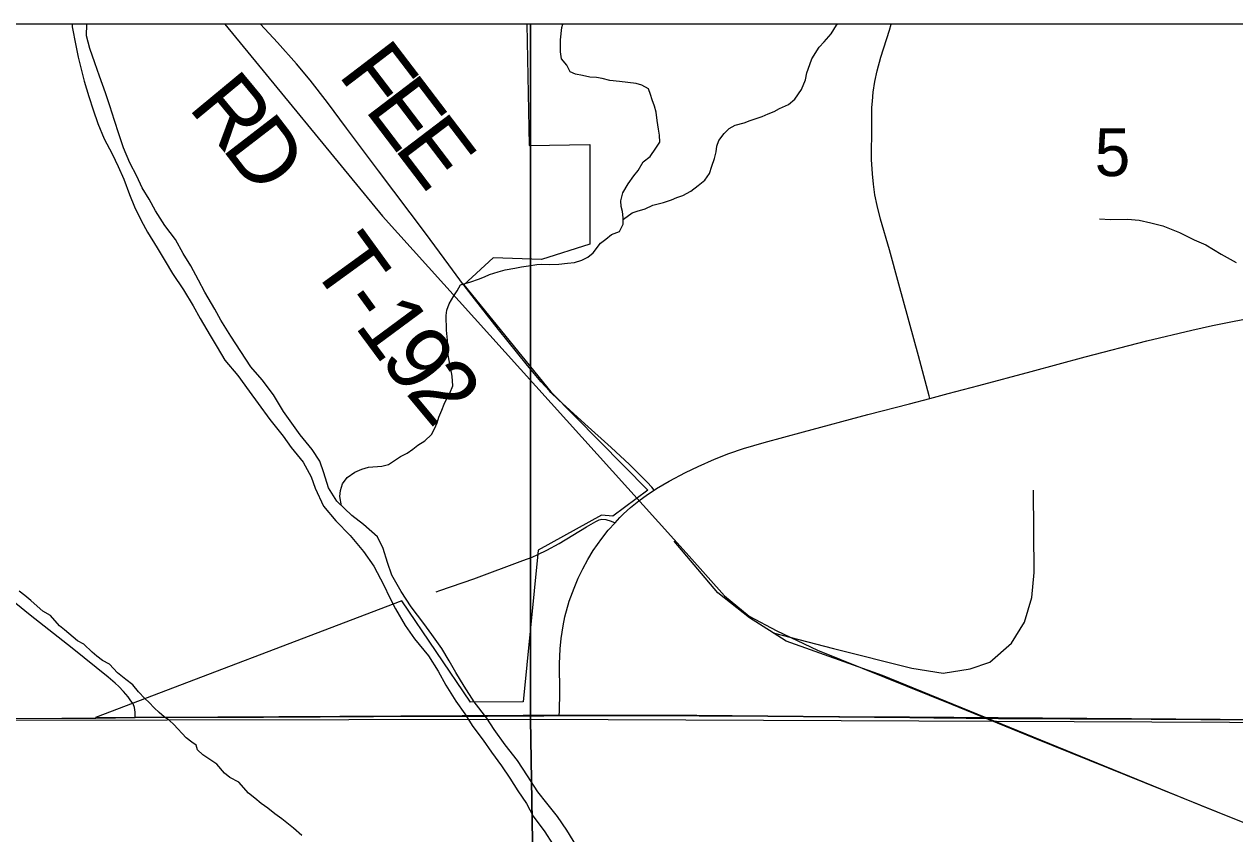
# Model space of a CAD drawing. Extents: x 0 to 34, y 0 to 22.
# Drawn here: x 6.446 to 7.505, y 20.191 to 20.9 of the extents above; entities that cross this region are included whole.
import ezdxf

# ---------------------------------------------------------------- set-up
doc = ezdxf.new("R2010")
doc.units = 0
for name, color, linetype in [('GM_X_City_Street', 7, 'Continuous'), ('GM_X_County_Road', 7, 'Continuous'), ('GM_X_Major_River', 7, 'Continuous'), ('GM_X_Minor_River', 7, 'Continuous'), ('GM_X_Rail_Line', 7, 'Continuous'), ('GM_X_Section', 7, 'Continuous'), ('GM_X_Section_Text', 7, 'Continuous'), ('GM_X_State_Route', 7, 'Continuous'), ('GM_X_Township_Road', 7, 'Continuous'), ('GM_X_Township_Road_Text', 7, 'Continuous'), ('GM_X_Unincorporated', 7, 'Continuous')]:
    doc.layers.add(name, color=color, linetype=linetype)

msp = doc.modelspace()

# ---------------------------------------------------------------- linework, layer by layer
at = {"layer": 'GM_X_City_Street'}
for points in [[(7.2385, 20.5724), (7.2379, 20.5746), (7.2285, 20.6096), (7.2112, 20.6725), (7.203, 20.7024), (7.1953, 20.7293), (7.1923, 20.7414), (7.1904, 20.7505), (7.189, 20.7598), (7.1881, 20.7691), (7.1875, 20.7816), (7.1876, 20.8112), (7.1878, 20.8269), (7.1881, 20.8325), (7.1888, 20.8406), (7.1902, 20.8499), (7.1922, 20.859), (7.1956, 20.871), (7.2031, 20.8947), (7.2045, 20.9)], [(6.8955, 20.4359), (6.9031, 20.4395), (6.9141, 20.4454), (6.938, 20.4599), (6.9461, 20.4645), (6.9491, 20.466), (6.9513, 20.4666), (6.955, 20.4663), (6.9595, 20.4648), (6.9629, 20.4636)]]:
    msp.add_lwpolyline(points, dxfattribs=at)
at = {"layer": 'GM_X_County_Road'}
for points in [[(6.382, 20.2915), (6.3969, 20.2916), (6.4231, 20.2921), (6.4788, 20.2924), (6.5063, 20.2926)], [(6.5063, 20.2926), (6.5086, 20.2926), (6.5431, 20.293)], [(6.5431, 20.293), (6.6552, 20.2934), (6.705, 20.2938), (6.7982, 20.2942), (6.8262, 20.2942)], [(6.8262, 20.2942), (6.8512, 20.2942), (6.8773, 20.2944), (6.8828, 20.2944), (6.8848, 20.2945)], [(6.8848, 20.2945), (6.9006, 20.2946), (6.9141, 20.2947)], [(6.9141, 20.2947), (7.0344, 20.2947), (7.2208, 20.293), (7.242, 20.2928)], [(7.242, 20.2928), (7.2985, 20.2922), (7.3611, 20.292)], [(7.3611, 20.292), (7.373, 20.292), (7.432, 20.2916), (7.519, 20.291), (7.5594, 20.2907), (7.5702, 20.2906)]]:
    msp.add_lwpolyline(points, dxfattribs=at)
at = {"layer": 'GM_X_Major_River'}
for points in [[(6.4877, 20.9), (6.4879, 20.8977), (6.491, 20.8814), (6.493, 20.8712), (6.4984, 20.85), (6.5023, 20.8367), (6.5062, 20.825), (6.5104, 20.8129), (6.5158, 20.7997), (6.5227, 20.7864), (6.5281, 20.7755), (6.5331, 20.7642), (6.5381, 20.7509), (6.5424, 20.74), (6.5481, 20.7282), (6.5539, 20.718), (6.5623, 20.7041), (6.5692, 20.6924), (6.5757, 20.6818), (6.5853, 20.6675), (6.5937, 20.6535), (6.5998, 20.6422), (6.6087, 20.6274), (6.6148, 20.6172), (6.6213, 20.6059), (6.6328, 20.5924), (6.6427, 20.5788), (6.6507, 20.5678), (6.6607, 20.5539), (6.6725, 20.5392), (6.6794, 20.5294), (6.6901, 20.5166), (6.697, 20.5037), (6.7005, 20.4939), (6.7078, 20.478), (6.7185, 20.4652), (6.7311, 20.4524), (6.7429, 20.4385), (6.7517, 20.4256), (6.7605, 20.409), (6.7655, 20.3984), (6.7709, 20.3882), (6.7793, 20.3735), (6.7874, 20.3618), (6.7996, 20.3471), (6.808, 20.3335), (6.8149, 20.3214), (6.8237, 20.3075), (6.8314, 20.2962), (6.8386, 20.2852), (6.8474, 20.2731), (6.8547, 20.2626), (6.8635, 20.2509), (6.8708, 20.2399), (6.878, 20.229), (6.8853, 20.2177), (6.8914, 20.2067), (6.9014, 20.1931), (6.9083, 20.1826)], [(6.5609, 20.7367), (6.5552, 20.7469), (6.5491, 20.7567), (6.5445, 20.7669), (6.5383, 20.7786), (6.5329, 20.7918), (6.5287, 20.8039), (6.5248, 20.8157), (6.5209, 20.8285), (6.5171, 20.8399), (6.5117, 20.8546), (6.5078, 20.866), (6.5032, 20.8788), (6.5004, 20.8898), (6.5007, 20.9)], [(6.9295, 20.1801), (6.9207, 20.1944), (6.9127, 20.2065), (6.9031, 20.2182), (6.8955, 20.228), (6.8863, 20.242), (6.8775, 20.2555), (6.8668, 20.2691), (6.8572, 20.2827), (6.8507, 20.2925), (6.8396, 20.3068), (6.8308, 20.3204), (6.8235, 20.3325), (6.8178, 20.3427), (6.8113, 20.3536), (6.8025, 20.3657), (6.7956, 20.3755), (6.7845, 20.3899), (6.7757, 20.4034), (6.7677, 20.4178), (6.7638, 20.4288), (6.7599, 20.4409), (6.7549, 20.4511), (6.7427, 20.462), (6.7325, 20.4699), (6.7195, 20.4823), (6.7122, 20.494), (6.708, 20.5072), (6.7045, 20.5174), (6.698, 20.5276), (6.6873, 20.5404), (6.6727, 20.5608), (6.6639, 20.5755), (6.654, 20.5887), (6.6441, 20.6), (6.6353, 20.6136), (6.6268, 20.6268), (6.618, 20.6408), (6.6127, 20.6506), (6.6039, 20.6653), (6.5985, 20.6759), (6.5916, 20.6884), (6.5851, 20.6993), (6.5782, 20.7114), (6.569, 20.7238), (6.5609, 20.7367)]]:
    msp.add_lwpolyline(points, dxfattribs=at)
at = {"layer": 'GM_X_Minor_River'}
for points in [[(6.7234, 20.4785), (6.7221, 20.4865), (6.7228, 20.4918), (6.7243, 20.4975), (6.7284, 20.5033), (6.7352, 20.5079), (6.7412, 20.5106), (6.7473, 20.5122), (6.7587, 20.5132), (6.7647, 20.5144), (6.7753, 20.5214), (6.781, 20.5245), (6.7859, 20.528), (6.7904, 20.5314), (6.7964, 20.5353), (6.8024, 20.5407), (6.805, 20.5457), (6.8072, 20.551), (6.8087, 20.556), (6.8113, 20.5621), (6.8135, 20.5674), (6.8157, 20.5724), (6.8183, 20.577), (6.8209, 20.5835), (6.8204, 20.5918), (6.8192, 20.5983), (6.8179, 20.6055), (6.8167, 20.6119), (6.8163, 20.618), (6.8162, 20.6233), (6.8153, 20.632), (6.8151, 20.645), (6.8158, 20.6495), (6.8177, 20.6552), (6.8218, 20.6621), (6.8248, 20.6667), (6.8277, 20.6717), (6.8368, 20.6745), (6.8433, 20.6769), (6.8486, 20.6788), (6.8531, 20.6808), (6.8607, 20.6832), (6.8667, 20.6848), (6.8751, 20.6864), (6.8812, 20.6876), (6.8872, 20.6885), (6.8944, 20.6897), (6.899, 20.6898), (6.9058, 20.6895), (6.9138, 20.69), (6.9214, 20.6908), (6.9275, 20.6913), (6.9339, 20.6933), (6.9392, 20.696), (6.9437, 20.6998), (6.9501, 20.7083), (6.955, 20.7118), (6.9599, 20.716), (6.9667, 20.7184), (6.97, 20.7249), (6.97, 20.7306), (6.9695, 20.7359), (6.9683, 20.7404), (6.9679, 20.7454), (6.9697, 20.7522), (6.9745, 20.7603), (6.9794, 20.7672), (6.9831, 20.7718), (6.9876, 20.7794), (6.9936, 20.7841), (6.9985, 20.7914), (7.0022, 20.7967), (7.0017, 20.8028), (7.0009, 20.8081), (6.9997, 20.8157), (6.9988, 20.8229), (6.9976, 20.8282), (6.9953, 20.8339), (6.9941, 20.8384), (6.9921, 20.8433), (6.9863, 20.8467), (6.9814, 20.8481), (6.9741, 20.8488), (6.9669, 20.8498), (6.9585, 20.8508), (6.9517, 20.8523), (6.9467, 20.8533), (6.941, 20.8536), (6.9345, 20.8551), (6.9284, 20.8561), (6.9238, 20.8584), (6.9207, 20.864), (6.9161, 20.8696), (6.9152, 20.8757), (6.9151, 20.8863), (6.9165, 20.897), (6.9173, 20.9)], [(6.97, 20.7294), (6.9704, 20.7294), (6.9779, 20.7349), (6.9824, 20.7364), (6.9893, 20.7384), (6.9961, 20.7416), (7.0052, 20.744), (7.0124, 20.7463), (7.0169, 20.7483), (7.0222, 20.7499), (7.0294, 20.7538), (7.0358, 20.7588), (7.0414, 20.7634), (7.0455, 20.7692), (7.0477, 20.7757), (7.0499, 20.7825), (7.0514, 20.7883), (7.0521, 20.7932), (7.0539, 20.7982), (7.0584, 20.8043), (7.0629, 20.8086), (7.0682, 20.8117), (7.0758, 20.8137), (7.0811, 20.8156), (7.0917, 20.8192), (7.097, 20.8215), (7.1023, 20.8235), (7.1068, 20.8262), (7.1147, 20.8298), (7.1204, 20.8344), (7.126, 20.8428), (7.1297, 20.8512), (7.1307, 20.8573), (7.1333, 20.8646), (7.1351, 20.8695), (7.1415, 20.8799), (7.146, 20.8845), (7.152, 20.8914), (7.1568, 20.8991), (7.1576, 20.9)], [(7.387, 20.7296), (7.3965, 20.7289), (7.4113, 20.7294), (7.4215, 20.7284), (7.4317, 20.7262), (7.4423, 20.7236), (7.4568, 20.7176), (7.4697, 20.7113), (7.48, 20.7068), (7.4933, 20.6986), (7.5066, 20.6915)], [(6.5768, 20.287), (6.5729, 20.2904), (6.5683, 20.2937), (6.5641, 20.2975), (6.5595, 20.3016), (6.5552, 20.3061), (6.5514, 20.3098), (6.546, 20.3155), (6.5409, 20.3218), (6.5348, 20.3263), (6.5275, 20.3323), (6.5205, 20.3398), (6.5144, 20.3431), (6.5094, 20.3469), (6.5052, 20.3502), (6.4979, 20.3574), (6.4925, 20.3603), (6.4887, 20.3633), (6.481, 20.3697), (6.4768, 20.3734), (6.469, 20.3824), (6.4621, 20.3861), (6.4571, 20.3906), (6.4517, 20.3955), (6.4464, 20.4), (6.4414, 20.4037)], [(6.6887, 20.1897), (6.6814, 20.1961), (6.6714, 20.2043), (6.6652, 20.2088), (6.6591, 20.2136), (6.6533, 20.2177), (6.6476, 20.2226), (6.6422, 20.2267), (6.6337, 20.2365), (6.6257, 20.2405), (6.6211, 20.2443), (6.6145, 20.2522), (6.6022, 20.2604), (6.5976, 20.2649), (6.5964, 20.269), (6.5926, 20.2716), (6.5876, 20.2754), (6.5841, 20.2791), (6.5802, 20.2832), (6.5768, 20.287)]]:
    msp.add_lwpolyline(points, dxfattribs=at)
at = {"layer": 'GM_X_Rail_Line'}
for points in [[(6.6213, 20.9), (6.7594, 20.7318), (7.0277, 20.4343), (7.0588, 20.3996), (7.0804, 20.3819), (7.1046, 20.369), (7.14, 20.352), (7.2574, 20.3046), (7.3294, 20.2753), (7.5064, 20.2037)], [(7.1013, 20.3673), (7.1542, 20.3535), (7.2226, 20.3364), (7.2502, 20.3318), (7.2738, 20.3357), (7.2909, 20.3416), (7.31, 20.3581), (7.3212, 20.3765), (7.3278, 20.3982), (7.3297, 20.4199), (7.3291, 20.4922)], [(7.1013, 20.3673), (7.0805, 20.3804), (7.0529, 20.4021), (7.0147, 20.4475)], [(7.771, 20.0976), (7.4757, 20.216), (7.1969, 20.3298), (7.1127, 20.36), (7.1013, 20.3673)]]:
    msp.add_lwpolyline(points, dxfattribs=at)
at = {"layer": 'GM_X_Section'}
for points in [[(5.776, 20.2897), (6.8888, 20.2917), (6.9057, 19.2783), (5.7801, 19.2683), (5.7798, 19.3134)], [(7.9084, 20.2871), (7.9079, 19.2721), (6.9057, 19.2783), (6.8888, 20.2917)]]:
    msp.add_lwpolyline(points, close=True, dxfattribs=at)
at = {"layer": 'GM_X_State_Route'}
for points in [[(6.5254, 20.323), (6.5192, 20.3284), (6.4877, 20.3537), (6.4512, 20.3827), (6.4052, 20.4197), (6.3711, 20.4466), (6.3615, 20.4546), (6.3546, 20.4609), (6.348, 20.4676), (6.3439, 20.4723), (6.3383, 20.4799), (6.3332, 20.4878), (6.3254, 20.5013), (6.2927, 20.5613), (6.2659, 20.6104), (6.2347, 20.6677), (6.2208, 20.6919), (6.2111, 20.7078), (6.1991, 20.7259), (6.169, 20.7694), (6.1406, 20.8102), (6.1056, 20.8615), (6.0793, 20.9)], [(8.9, 20.9), (6.8857, 20.9), (6.8878, 20.7937), (6.941, 20.7946), (6.9408, 20.7075), (6.8986, 20.6939), (6.8562, 20.6954), (6.8305, 20.6718), (6.9066, 20.5782), (6.9916, 20.4921), (6.961, 20.4692), (6.951, 20.4702), (6.8957, 20.4395), (6.8953, 20.4364), (6.8826, 20.3069), (6.8364, 20.3065), (6.7763, 20.3953), (6.5084, 20.2932), (6.8825, 20.295), (6.9139, 20.2952), (7.2206, 20.2936), (7.57, 20.2911)], [(6.5431, 20.293), (6.5429, 20.2978), (6.5428, 20.2999), (6.5423, 20.3019), (6.5411, 20.3049), (6.5393, 20.3078), (6.5369, 20.3113), (6.5329, 20.3159), (6.5286, 20.3203), (6.5254, 20.323)], [(6.8262, 20.2942), (6.7982, 20.2942), (6.705, 20.2938), (6.6552, 20.2934), (6.5431, 20.293)], [(6.8848, 20.2945), (6.8828, 20.2944), (6.8773, 20.2944), (6.8512, 20.2942), (6.8262, 20.2942)], [(6.9141, 20.2947), (6.9006, 20.2946), (6.8848, 20.2945)], [(7.242, 20.2928), (7.2208, 20.293), (7.0344, 20.2947), (6.9141, 20.2947)], [(7.3611, 20.292), (7.2985, 20.2922), (7.242, 20.2928)], [(7.5702, 20.2906), (7.5594, 20.2907), (7.519, 20.291), (7.432, 20.2916), (7.373, 20.292), (7.3611, 20.292)]]:
    msp.add_lwpolyline(points, dxfattribs=at)
at = {"layer": 'GM_X_Township_Road'}
for points in [[(8.9, 17.2634), (8.9, 20.9), (5.7818, 20.9)], [(6.8309, 20.6711), (6.8303, 20.6718), (6.8174, 20.6894), (6.7971, 20.7169), (6.756, 20.7716), (6.728, 20.8089), (6.7113, 20.8314), (6.696, 20.851), (6.6841, 20.8654), (6.6676, 20.8839), (6.6526, 20.9)], [(6.9057, 20.5789), (6.8983, 20.5868), (6.8863, 20.6011), (6.861, 20.6326), (6.8398, 20.6595), (6.8309, 20.6711)], [(7.2385, 20.5724), (7.2544, 20.5767), (7.2813, 20.5838), (7.3271, 20.596), (7.3744, 20.6088), (7.4284, 20.6229), (7.4676, 20.6321), (7.4857, 20.6362), (7.5283, 20.6446), (7.5587, 20.6505), (7.5673, 20.6521)], [(6.9973, 20.4922), (6.995, 20.4946), (6.9909, 20.4991), (6.9755, 20.5145), (6.9596, 20.5293), (6.9366, 20.5502), (6.9135, 20.5711), (6.9068, 20.5776), (6.9057, 20.5789)], [(6.9973, 20.4922), (6.9992, 20.4934), (7.0104, 20.5), (7.0245, 20.5076), (7.0356, 20.5128), (7.0501, 20.5191), (7.0624, 20.5241), (7.0754, 20.5285), (7.0935, 20.5338), (7.1279, 20.543), (7.1843, 20.5582), (7.2207, 20.5677), (7.2385, 20.5724)], [(6.9629, 20.4636), (6.967, 20.468), (6.9704, 20.4713), (6.9766, 20.4769), (6.9838, 20.4828), (6.9914, 20.4883), (6.9973, 20.4922)], [(6.9141, 20.2947), (6.9142, 20.2987), (6.9145, 20.3152), (6.9144, 20.3401), (6.915, 20.3533), (6.9157, 20.3621), (6.9175, 20.3733), (6.919, 20.3811), (6.9227, 20.3949), (6.9271, 20.4064), (6.9306, 20.4149), (6.9347, 20.4232), (6.9391, 20.4313), (6.9439, 20.4392), (6.9513, 20.4497), (6.957, 20.4571), (6.9629, 20.4636)], [(6.8065, 20.4031), (6.8095, 20.4042), (6.8394, 20.4146), (6.8823, 20.4304), (6.8903, 20.4335), (6.8955, 20.4359)]]:
    msp.add_lwpolyline(points, dxfattribs=at)
at = {"layer": 'GM_X_Unincorporated'}
for points in [[(6.889, 20.9), (5.7777, 20.9), (5.7762, 20.3113), (5.776, 20.2897), (6.8888, 20.2917)], [(7.9104, 20.9), (6.889, 20.9), (6.8888, 20.2917), (7.9084, 20.2871)]]:
    msp.add_lwpolyline(points, close=True, dxfattribs=at)

# ---------------------------------------------------------------- texts
at = {"layer": 'GM_X_Section_Text'}
msp.add_text('5', height=0.0419, rotation=0, dxfattribs=at).set_placement((7.3827, 20.767))
at = {"layer": 'GM_X_Township_Road_Text'}
for s, rotation, p in [('F', 307.3693, (6.7198, 20.8558)), ('R', 309.6479, (6.5886, 20.8269)), ('E', 307.2779, (6.743, 20.8254)), ('D', 307.6076, (6.6181, 20.7914)), ('E', 307.2766, (6.7688, 20.7915)), ('T', 305.9639, (6.6952, 20.6895)), ('-', 306.068, (6.7202, 20.655)), ('1', 306.495, (6.7343, 20.6358)), ('9', 308.0277, (6.7561, 20.6063)), ('2', 309.7399, (6.7788, 20.5773))]:
    msp.add_text(s, height=0.0568, rotation=rotation, dxfattribs=at).set_placement(p)

doc.saveas('drawing.dxf')
